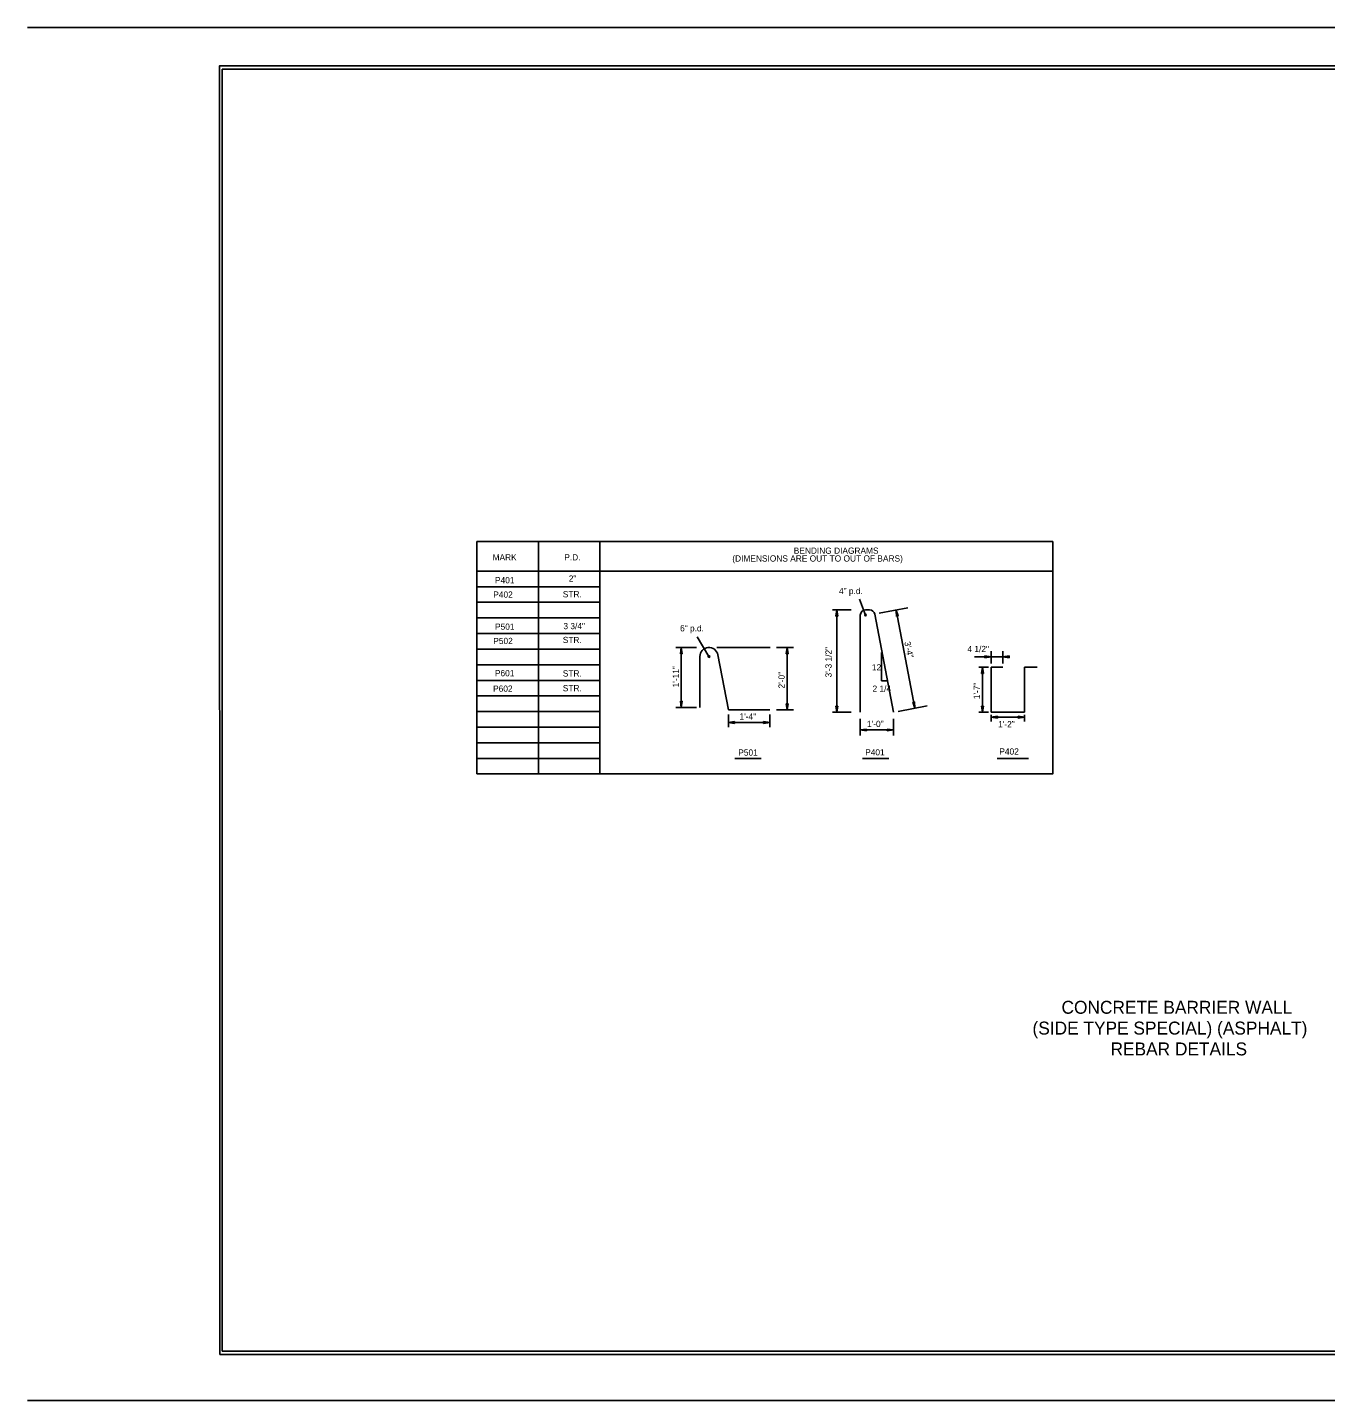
# Model space of a CAD drawing. Extents: x 714919 to 718439, y 1619644 to 1621844.
# Drawn here: x 714919 to 717000, y 1619644 to 1621844 of the extents above; entities that cross this region are included whole.
import ezdxf

# ---------------------------------------------------------------- set-up
doc = ezdxf.new("R2010")
doc.units = 0
for name, color, linetype in [('R_Annotation', 7, 'Continuous'), ('R_Border', 7, 'Continuous'), ('R_Dimension', 7, 'Continuous'), ('R_Draft', 7, 'Continuous'), ('R_No Plot', 7, 'Continuous')]:
    doc.layers.add(name, color=color, linetype=linetype)

msp = doc.modelspace()

# ---------------------------------------------------------------- linework, layer by layer
at = {"layer": 'R_Border'}
for p, q in [((718438.8, 1621843.9), (714918.8, 1621843.6)), ((715231, 1619722.6), (715231.1, 1621777.2)), ((715231.1, 1621777.2), (718392.9, 1621777.2)), ((718393, 1619722.6), (715231, 1619722.6)), ((714918.9, 1619643.7), (718439.1, 1619643.9))]:
    msp.add_line(p, q, dxfattribs=at)
at = {"layer": 'R_Dimension'}
for p, q in [((716214.8, 1620900.6), (716216.3, 1620910.6)), ((716214.8, 1620900.6), (716217.8, 1620900.6)), ((716215, 1620900.6), (716216.3, 1620908.9)), ((716215.3, 1620900.6), (716216.3, 1620907.2)), ((716215.5, 1620900.6), (716216.3, 1620905.5)), ((716215.8, 1620900.6), (716216.3, 1620903.9)), ((716216, 1620900.6), (716216.3, 1620902.2)), ((716217.8, 1620900.6), (716216.3, 1620910.6)), ((716217.5, 1620900.6), (716216.3, 1620908.9)), ((716217.3, 1620900.6), (716216.3, 1620907.2)), ((716217, 1620900.6), (716216.3, 1620905.5)), ((716216.8, 1620900.6), (716216.3, 1620903.9)), ((716216.5, 1620900.6), (716216.3, 1620902.2)), ((716314.5, 1620900.8), (716311.2, 1620910.3)), ((716311.6, 1620900.2), (716311.2, 1620910.3)), ((716314.3, 1620900.8), (716311.5, 1620908.7)), ((716311.8, 1620900.3), (716311.5, 1620908.7)), ((716314.5, 1620900.8), (716311.6, 1620900.2)), ((716312.1, 1620900.3), (716311.8, 1620907)), ((716314, 1620900.7), (716311.8, 1620907)), ((716313.8, 1620900.7), (716312.1, 1620905.4)), ((716312.3, 1620900.4), (716312.1, 1620905.4)), ((716312.6, 1620900.4), (716312.4, 1620903.7)), ((716313.5, 1620900.6), (716312.4, 1620903.7)), ((716312.8, 1620900.5), (716312.7, 1620902.1)), ((716313.3, 1620900.6), (716312.7, 1620902.1)), ((715965.4, 1620840.3), (715966.9, 1620850.3)), ((715965.4, 1620840.3), (715968.4, 1620840.3)), ((715965.7, 1620840.3), (715966.9, 1620848.6)), ((715965.9, 1620840.3), (715966.9, 1620846.9)), ((715966.2, 1620840.3), (715966.9, 1620845.2)), ((715966.5, 1620840.3), (715966.9, 1620843.6)), ((715966.7, 1620840.3), (715966.9, 1620841.9)), ((715968.4, 1620840.3), (715966.9, 1620850.3)), ((715968.2, 1620840.3), (715966.9, 1620848.6)), ((715967.9, 1620840.3), (715966.9, 1620846.9)), ((715967.7, 1620840.3), (715966.9, 1620845.2)), ((715967.4, 1620840.3), (715966.9, 1620843.6)), ((715967.2, 1620840.3), (715966.9, 1620841.9)), ((716135, 1620840.3), (716136.5, 1620850.3)), ((716135, 1620840.3), (716138, 1620840.3)), ((716135.3, 1620840.3), (716136.5, 1620848.6)), ((716135.5, 1620840.3), (716136.5, 1620846.9)), ((716135.8, 1620840.3), (716136.5, 1620845.2)), ((716136.1, 1620840.3), (716136.5, 1620843.6)), ((716136.3, 1620840.3), (716136.5, 1620841.9)), ((716138, 1620840.3), (716136.5, 1620850.3)), ((716137.8, 1620840.3), (716136.5, 1620848.6)), ((716137.5, 1620840.3), (716136.5, 1620846.9)), ((716137.3, 1620840.3), (716136.5, 1620845.2)), ((716137, 1620840.3), (716136.5, 1620843.6)), ((716136.8, 1620840.3), (716136.5, 1620841.9)), ((716453.5, 1620836.8), (716463.5, 1620835.3)), ((716453.5, 1620836.8), (716453.5, 1620833.8)), ((716453.5, 1620836.6), (716461.8, 1620835.3)), ((716453.5, 1620836.3), (716460.1, 1620835.3)), ((716453.5, 1620836.1), (716458.4, 1620835.3)), ((716453.5, 1620835.8), (716456.7, 1620835.3)), ((716453.5, 1620835.6), (716455.1, 1620835.3)), ((716453.5, 1620833.8), (716463.5, 1620835.3)), ((716453.5, 1620834.9), (716456.7, 1620835.3)), ((716453.5, 1620834.4), (716460.1, 1620835.3)), ((716453.5, 1620834.1), (716461.8, 1620835.3)), ((716453.5, 1620834.6), (716458.4, 1620835.3)), ((716453.5, 1620835.1), (716455.1, 1620835.3)), ((716492.2, 1620836.8), (716482.2, 1620835.3)), ((716492.2, 1620833.8), (716482.2, 1620835.3)), ((716492.2, 1620836.6), (716483.8, 1620835.3)), ((716492.2, 1620834.1), (716483.8, 1620835.3)), ((716492.2, 1620836.3), (716485.6, 1620835.3)), ((716492.2, 1620834.4), (716485.6, 1620835.3)), ((716492.2, 1620836.1), (716487.2, 1620835.3)), ((716492.2, 1620834.6), (716487.2, 1620835.3)), ((716492.2, 1620835.8), (716488.9, 1620835.3)), ((716492.2, 1620834.9), (716488.9, 1620835.3)), ((716492.2, 1620835.6), (716490.6, 1620835.3)), ((716492.2, 1620835.1), (716490.6, 1620835.3)), ((716492.2, 1620836.8), (716492.2, 1620833.8)), ((716448.3, 1620808.9), (716449.8, 1620818.9)), ((716448.3, 1620808.9), (716451.3, 1620808.9)), ((716448.6, 1620808.9), (716449.8, 1620817.2)), ((716448.8, 1620808.9), (716449.8, 1620815.5)), ((716449.1, 1620808.9), (716449.8, 1620813.8)), ((716449.3, 1620808.9), (716449.8, 1620812.1)), ((716449.6, 1620808.9), (716449.8, 1620810.5)), ((716451.3, 1620808.9), (716449.8, 1620818.9)), ((716451.1, 1620808.9), (716449.8, 1620817.2)), ((716450.8, 1620808.9), (716449.8, 1620815.5)), ((716450.6, 1620808.9), (716449.8, 1620813.8)), ((716450.3, 1620808.9), (716449.8, 1620812.1)), ((716450, 1620808.9), (716449.8, 1620810.5)), ((715965.4, 1620764.3), (715966.9, 1620754.3)), ((715965.4, 1620764.3), (715968.4, 1620764.3)), ((715965.7, 1620764.3), (715966.9, 1620756)), ((715965.9, 1620764.3), (715966.9, 1620757.7)), ((715966.2, 1620764.3), (715966.9, 1620759.4)), ((715966.5, 1620764.3), (715966.9, 1620761.1)), ((715966.7, 1620764.3), (715966.9, 1620762.7)), ((715968.4, 1620764.3), (715966.9, 1620754.3)), ((715967.4, 1620764.3), (715966.9, 1620761.1)), ((715967.9, 1620764.3), (715966.9, 1620757.7)), ((715968.2, 1620764.3), (715966.9, 1620756)), ((715967.7, 1620764.3), (715966.9, 1620759.4)), ((715967.2, 1620764.3), (715966.9, 1620762.7)), ((716135, 1620760.3), (716136.5, 1620750.3)), ((716135, 1620760.3), (716138, 1620760.3)), ((716135.3, 1620760.3), (716136.5, 1620752)), ((716135.5, 1620760.3), (716136.5, 1620753.7)), ((716135.8, 1620760.3), (716136.5, 1620755.4)), ((716136.1, 1620760.3), (716136.5, 1620757.1)), ((716136.3, 1620760.3), (716136.5, 1620758.7)), ((716138, 1620760.3), (716136.5, 1620750.3)), ((716137, 1620760.3), (716136.5, 1620757.1)), ((716137.5, 1620760.3), (716136.5, 1620753.7)), ((716137.8, 1620760.3), (716136.5, 1620752)), ((716137.3, 1620760.3), (716136.5, 1620755.4)), ((716136.8, 1620760.3), (716136.5, 1620758.7)), ((716214.8, 1620756.5), (716216.3, 1620746.5)), ((716214.8, 1620756.5), (716217.8, 1620756.5)), ((716215, 1620756.5), (716216.3, 1620748.1)), ((716215.3, 1620756.5), (716216.3, 1620749.9)), ((716215.5, 1620756.5), (716216.3, 1620751.5)), ((716215.8, 1620756.5), (716216.3, 1620753.2)), ((716216, 1620756.5), (716216.3, 1620754.9)), ((716217.8, 1620756.5), (716216.3, 1620746.5)), ((716216.8, 1620756.5), (716216.3, 1620753.2)), ((716217.3, 1620756.5), (716216.3, 1620749.9)), ((716217.5, 1620756.5), (716216.3, 1620748.1)), ((716217, 1620756.5), (716216.3, 1620751.5)), ((716216.5, 1620756.5), (716216.3, 1620754.9)), ((716337.8, 1620762.5), (716340.7, 1620763.1)), ((716337.8, 1620762.5), (716341.1, 1620753)), ((716338, 1620762.6), (716340.8, 1620754.6)), ((716338.3, 1620762.6), (716340.5, 1620756.3)), ((716338.5, 1620762.7), (716340.2, 1620758)), ((716338.8, 1620762.7), (716339.9, 1620759.6)), ((716339, 1620762.8), (716339.6, 1620761.3)), ((716339.5, 1620762.9), (716339.6, 1620761.3)), ((716339.7, 1620762.9), (716339.9, 1620759.6)), ((716340, 1620763), (716340.2, 1620758)), ((716340.2, 1620763), (716340.5, 1620756.3)), ((716340.5, 1620763.1), (716340.8, 1620754.6)), ((716340.7, 1620763.1), (716341.1, 1620753)), ((716448.3, 1620756.5), (716449.8, 1620746.5)), ((716448.3, 1620756.5), (716451.3, 1620756.5)), ((716448.6, 1620756.5), (716449.8, 1620748.1)), ((716448.8, 1620756.5), (716449.8, 1620749.9)), ((716449.1, 1620756.5), (716449.8, 1620751.5)), ((716449.3, 1620756.5), (716449.8, 1620753.2)), ((716449.6, 1620756.5), (716449.8, 1620754.9)), ((716451.3, 1620756.5), (716449.8, 1620746.5)), ((716450.3, 1620756.5), (716449.8, 1620753.2)), ((716450.8, 1620756.5), (716449.8, 1620749.9)), ((716451.1, 1620756.5), (716449.8, 1620748.1)), ((716450.6, 1620756.5), (716449.8, 1620751.5)), ((716450, 1620756.5), (716449.8, 1620754.9)), ((716052.3, 1620731.7), (716042.3, 1620730.2)), ((716052.3, 1620728.7), (716042.3, 1620730.2)), ((716052.3, 1620731.5), (716044, 1620730.2)), ((716052.3, 1620729), (716044, 1620730.2)), ((716052.3, 1620731.2), (716045.7, 1620730.2)), ((716052.3, 1620729.2), (716045.7, 1620730.2)), ((716052.3, 1620731), (716047.4, 1620730.2)), ((716052.3, 1620729.5), (716047.4, 1620730.2)), ((716052.3, 1620730.7), (716049.1, 1620730.2)), ((716052.3, 1620729.7), (716049.1, 1620730.2)), ((716052.3, 1620730.5), (716050.7, 1620730.2)), ((716052.3, 1620730), (716050.7, 1620730.2)), ((716052.3, 1620731.7), (716052.3, 1620728.7)), ((716098.8, 1620731.7), (716108.8, 1620730.2)), ((716098.8, 1620731.7), (716098.8, 1620728.7)), ((716098.8, 1620731.5), (716107.1, 1620730.2)), ((716098.8, 1620731.2), (716105.4, 1620730.2)), ((716098.8, 1620731), (716103.8, 1620730.2)), ((716098.8, 1620730.7), (716102.1, 1620730.2)), ((716098.8, 1620730.5), (716100.4, 1620730.2)), ((716098.8, 1620728.7), (716108.8, 1620730.2)), ((716098.8, 1620729.7), (716102.1, 1620730.2)), ((716098.8, 1620729.2), (716105.4, 1620730.2)), ((716098.8, 1620729), (716107.1, 1620730.2)), ((716098.8, 1620729.5), (716103.8, 1620730.2)), ((716098.8, 1620730), (716100.4, 1620730.2)), ((716263.8, 1620719.7), (716253.8, 1620718.2)), ((716263.8, 1620719.7), (716263.8, 1620716.7)), ((716296.9, 1620719.7), (716306.9, 1620718.2)), ((716296.9, 1620719.7), (716296.9, 1620716.7)), ((716473.5, 1620740.3), (716463.5, 1620738.8)), ((716473.5, 1620737.3), (716463.5, 1620738.8)), ((716473.5, 1620740.1), (716465.1, 1620738.8)), ((716473.5, 1620737.6), (716465.1, 1620738.8)), ((716473.5, 1620739.8), (716466.9, 1620738.8)), ((716473.5, 1620737.8), (716466.9, 1620738.8)), ((716473.5, 1620739.6), (716468.5, 1620738.8)), ((716473.5, 1620738.1), (716468.5, 1620738.8)), ((716473.5, 1620739.3), (716470.2, 1620738.8)), ((716473.5, 1620738.3), (716470.2, 1620738.8)), ((716473.5, 1620739), (716471.9, 1620738.8)), ((716473.5, 1620738.6), (716471.9, 1620738.8)), ((716473.5, 1620740.3), (716473.5, 1620737.3)), ((716506.8, 1620740.3), (716516.8, 1620738.8)), ((716506.8, 1620740.3), (716506.8, 1620737.3)), ((716506.8, 1620740.1), (716515.1, 1620738.8)), ((716506.8, 1620739.8), (716513.4, 1620738.8)), ((716506.8, 1620739.6), (716511.7, 1620738.8)), ((716506.8, 1620739.3), (716510, 1620738.8)), ((716506.8, 1620739), (716508.4, 1620738.8)), ((716506.8, 1620737.3), (716516.8, 1620738.8)), ((716506.8, 1620738.3), (716510, 1620738.8)), ((716506.8, 1620737.8), (716513.4, 1620738.8)), ((716506.8, 1620737.6), (716515.1, 1620738.8)), ((716506.8, 1620738.1), (716511.7, 1620738.8)), ((716506.8, 1620738.6), (716508.4, 1620738.8)), ((716263.8, 1620716.7), (716253.8, 1620718.2)), ((716263.8, 1620719.5), (716255.4, 1620718.2)), ((716263.8, 1620717), (716255.4, 1620718.2)), ((716263.8, 1620719.2), (716257.2, 1620718.2)), ((716263.8, 1620717.2), (716257.2, 1620718.2)), ((716263.8, 1620719), (716258.8, 1620718.2)), ((716263.8, 1620717.5), (716258.8, 1620718.2)), ((716263.8, 1620718.7), (716260.5, 1620718.2)), ((716263.8, 1620717.7), (716260.5, 1620718.2)), ((716263.8, 1620718.5), (716262.2, 1620718.2)), ((716263.8, 1620718), (716262.2, 1620718.2)), ((716296.9, 1620719.5), (716305.3, 1620718.2)), ((716296.9, 1620719.2), (716303.5, 1620718.2)), ((716296.9, 1620719), (716301.9, 1620718.2)), ((716296.9, 1620718.7), (716300.2, 1620718.2)), ((716296.9, 1620718.5), (716298.5, 1620718.2)), ((716296.9, 1620716.7), (716306.9, 1620718.2)), ((716296.9, 1620717.7), (716300.2, 1620718.2)), ((716296.9, 1620717.2), (716303.5, 1620718.2)), ((716296.9, 1620717), (716305.3, 1620718.2)), ((716296.9, 1620717.5), (716301.9, 1620718.2)), ((716296.9, 1620718), (716298.5, 1620718.2))]:
    msp.add_line(p, q, dxfattribs=at)
at = {"layer": 'R_Draft'}
for p, q in [((715737.9, 1621020), (715737.9, 1620647.7)), ((715836.5, 1621020), (715836.5, 1620722.7)), ((715639.2, 1620972.7), (715836.5, 1620972.7)), ((715639.2, 1620972.7), (715639.2, 1620647.7)), ((716562.3, 1620972.7), (715836.5, 1620972.7)), ((715639.2, 1620947.7), (715836.5, 1620947.7)), ((715639.2, 1620922.7), (715836.5, 1620922.7)), ((716252.5, 1620927.5), (716262.1, 1620902.3)), ((715639.2, 1620897.7), (715836.5, 1620897.7)), ((716239, 1620910.6), (716209.3, 1620910.6)), ((716216.3, 1620746.5), (716216.3, 1620910.6)), ((716253.8, 1620902.3), (716253.8, 1620746.5)), ((716262.1, 1620910.6), (716268.8, 1620910.6)), ((716277, 1620903.8), (716306.9, 1620746.5)), ((716329.9, 1620913.9), (716284.3, 1620905.2)), ((716341.1, 1620753), (716311.2, 1620910.3)), ((715639.2, 1620872.7), (715836.5, 1620872.7)), ((715992.4, 1620867.4), (716011.2, 1620835.8)), ((715639.2, 1620847.7), (715836.5, 1620847.7)), ((715991.2, 1620850.3), (715958, 1620850.3)), ((715966.9, 1620850.3), (715966.9, 1620754.3)), ((715996.6, 1620835.8), (715996.6, 1620754.3)), ((716023.9, 1620850.3), (716109.5, 1620850.3)), ((716025.5, 1620838.5), (716042.3, 1620750.3)), ((716146.7, 1620850.3), (716119.3, 1620850.3)), ((716136.5, 1620850.3), (716136.5, 1620750.3)), ((716288, 1620796.8), (716288, 1620842.2)), ((716482.2, 1620835.3), (716437.1, 1620835.3)), ((716463.5, 1620844.3), (716463.5, 1620824.8)), ((716482.2, 1620844.3), (716482.2, 1620824.8)), ((715639.2, 1620822.7), (715836.5, 1620822.7)), ((716443.6, 1620818.9), (716459.3, 1620818.9)), ((716449.8, 1620746.5), (716449.8, 1620818.9)), ((716463.5, 1620818.9), (716463.5, 1620746.5)), ((716463.5, 1620818.9), (716482.2, 1620818.9)), ((716516.8, 1620818.9), (716516.8, 1620746.5)), ((716516.8, 1620818.9), (716537.1, 1620818.9)), ((715639.2, 1620797.7), (715836.5, 1620797.7)), ((716295.8, 1620796.8), (716288, 1620796.8)), ((715639.2, 1620772.7), (715836.5, 1620772.7)), ((715639.2, 1620747.7), (715836.5, 1620747.7)), ((715991.2, 1620754.3), (715958, 1620754.3)), ((716042.3, 1620750.3), (716108.8, 1620750.3)), ((716042.3, 1620722.5), (716042.3, 1620743.1)), ((716108.8, 1620722.5), (716108.8, 1620743.1)), ((716146.7, 1620750.3), (716119.3, 1620750.3)), ((716239, 1620746.5), (716209.3, 1620746.5)), ((716360.8, 1620756.7), (716314.3, 1620747.9)), ((716443.6, 1620746.5), (716459.3, 1620746.5)), ((716463.5, 1620746.5), (716516.8, 1620746.5)), ((716463.5, 1620731.7), (716463.5, 1620742.5)), ((716516.8, 1620731.7), (716516.8, 1620742.5)), ((715639.2, 1620722.7), (715836.5, 1620722.7)), ((716108.8, 1620730.2), (716042.3, 1620730.2)), ((716253.8, 1620736.1), (716253.8, 1620709.4)), ((716306.9, 1620736.1), (716306.9, 1620709.4)), ((716516.8, 1620738.8), (716463.5, 1620738.8)), ((715639.2, 1620697.7), (715836.5, 1620697.7)), ((716306.9, 1620718.2), (716253.8, 1620718.2)), ((715639.2, 1620672.7), (715836.5, 1620672.7)), ((716052.5, 1620672.7), (716094.8, 1620672.7)), ((716257.4, 1620672.7), (716299.7, 1620672.7)), ((716473.3, 1620672.7), (716523.3, 1620672.7)), ((715639.2, 1620647.7), (715836.5, 1620647.7))]:
    msp.add_line(p, q, dxfattribs=at)
for points in [[(716562.3, 1620972.7), (715639.2, 1620972.7), (715639.2, 1621020), (716562.3, 1621020)], [(715836.5, 1620647.7), (716562.3, 1620647.7), (716562.3, 1620972.7), (715836.5, 1620972.7)]]:
    msp.add_lwpolyline(points, close=True, dxfattribs=at)
for centre in [(716262.1, 1620902.3), (716011.2, 1620835.8)]:
    msp.add_circle(centre, 1.3, dxfattribs=at)
for centre, radius, start, end in [((716262.1, 1620902.3), 8.33, 90, 180), ((716268.8, 1620902.3), 8.33, 10.7843, 90), ((716011.2, 1620835.8), 14.6, 10.7843, 180)]:
    msp.add_arc(centre, radius, start, end, dxfattribs=at)
at = {"layer": 'R_No Plot'}
msp.add_lwpolyline([(715227, 1619717.4), (718396.9, 1619717.5), (718397, 1621782.6), (715226.9, 1621782.4)], close=True, dxfattribs=at)

# ---------------------------------------------------------------- texts
at = {"layer": 'R_Annotation'}
for s, p in [('CONCRETE BARRIER WALL ', (716576.3, 1620263.4)), ('(SIDE TYPE SPECIAL) (ASPHALT)', (716529.8, 1620230.1)), ('REBAR DETAILS', (716654.9, 1620196.7))]:
    msp.add_text(s, height=20.736, dxfattribs=at).set_placement(p)
at = {"layer": 'R_Draft'}
for s, p in [('BENDING DIAGRAMS', (716147.1, 1621000.5)), ('MARK', (715664.4, 1620989.8)), ('P.D.', (715779.3, 1620989.8)), ('(DIMENSIONS ARE OUT TO OUT OF BARS)', (716048.6, 1620988)), ('P401', (715668.3, 1620953.2)), ('2"', (715786.5, 1620955.7)), ('P402', (715665.5, 1620930.1)), ('STR.', (715776.9, 1620930.7)), ('4" p.d.', (716219.6, 1620935.9)), ('P501', (715668.3, 1620878.7)), ('3 3/4"', (715777.9, 1620879.7)), ('6" p.d.', (715964.9, 1620876.1)), ('P502', (715665.5, 1620855.8)), ('STR.', (715776.9, 1620857.4)), ('4 1/2"', (716425.5, 1620842.9)), ('P601', (715668.1, 1620804.2)), ('STR.', (715776.9, 1620803.8)), ('12', (716272.4, 1620813.5)), ('P602', (715665.2, 1620779.4)), ('STR.', (715776.9, 1620780.2)), ('2 1/4', (716273.4, 1620779.3)), ('1\'-4"', (716060.2, 1620734.8)), ('1\'-0"', (716264.5, 1620722.9)), ('1\'-2"', (716474.7, 1620722.4)), ('P501', (716058.2, 1620677)), ('P401', (716261.6, 1620677.4)), ('P402', (716476.7, 1620678.7))]:
    msp.add_text(s, height=10, dxfattribs=at).set_placement(p)
for s, rotation, p in [('3\'-4"', 281.4827, (716324.3, 1620858.9)), ('3\'-3 1/2"', 90, (716207.8, 1620802.3)), ('1\'-11"', 90, (715963, 1620786.4)), ('2\'-0"', 90, (716132.6, 1620784.6)), ('1\'-7"', 90, (716445.5, 1620767.4))]:
    msp.add_text(s, height=10, rotation=rotation, dxfattribs=at).set_placement(p)

doc.saveas('drawing.dxf')
